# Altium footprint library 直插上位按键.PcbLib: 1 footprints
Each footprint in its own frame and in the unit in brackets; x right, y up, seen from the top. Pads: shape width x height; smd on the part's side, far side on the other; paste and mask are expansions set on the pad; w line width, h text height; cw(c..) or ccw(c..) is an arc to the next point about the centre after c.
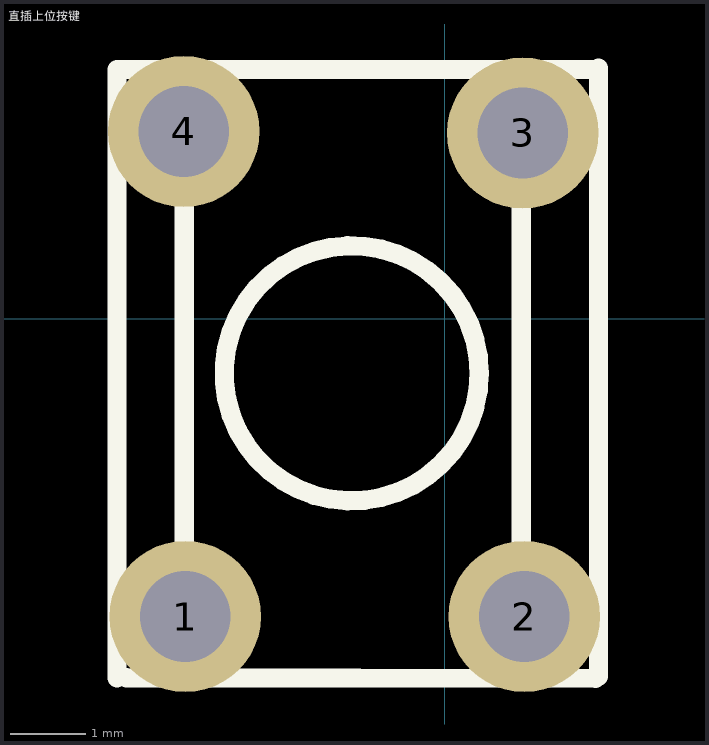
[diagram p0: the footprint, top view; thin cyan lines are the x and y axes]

## 直插上位按键 [mm] "直插上位按键"
pads (4):
  round 2 hole 1.2: 1(-3.429,-3.937) 2(1.051,-3.937) 3(1.031,2.453) 4(-3.449,2.473)
Top Overlay:
  circle w0.254: c-1.229,-0.723 r1.686
  lines w0.254: -4.331,-4.747 -4.331,3.291 2.033,3.291 ; -4.204,-4.747 1.991,-4.757 ; -3.442,-3.858 -3.442,2.746 ; 1.011,-3.774 1.011,2.703 ; 2.031,-4.729 2.031,3.313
